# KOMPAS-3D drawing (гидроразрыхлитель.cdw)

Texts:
  ВНЕШНИЙ ВИД  ГИДРОРАЗРЫХЛИТЕЛЯ
  Текст на чертеже
  Размерные надписи
  Шероховатость
  Линия-выноска #1
  Линия-выноска #2
  Линия-выноска #3
  Отклонения формы и база
  Заголовок таблицы
  Ячейка таблицы
  Стрелка вида
  Обозначение изменения
  Фигурная скобка
  Номер узла
  Марка координационной оси
  VRCB
  Выносная надпись
  Обозначение узла
  Марка/позиционное обозначение с линией-выноской
  Марка/позиционное обозначение на линии
  Марка/позиционное обозначение без линии-выноски
  Основные габариты
  Длина гидроразрыхлителя         14,8м
  Ширина наибольшая                3,45м
  Диаметр всасывающего трубопровода
  составляет                            1м
  Диаметр нагнетательного трубопро
  да составляет                     0,35м
  Мощность насосной станции   55кВт
  ВНЕШНИЙ ВИД
  Матюшко А.Н.
Dimensions and other numbers on the sheet: 7; 1; 0; 2; 3; 4; 5; 6; 8; 9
